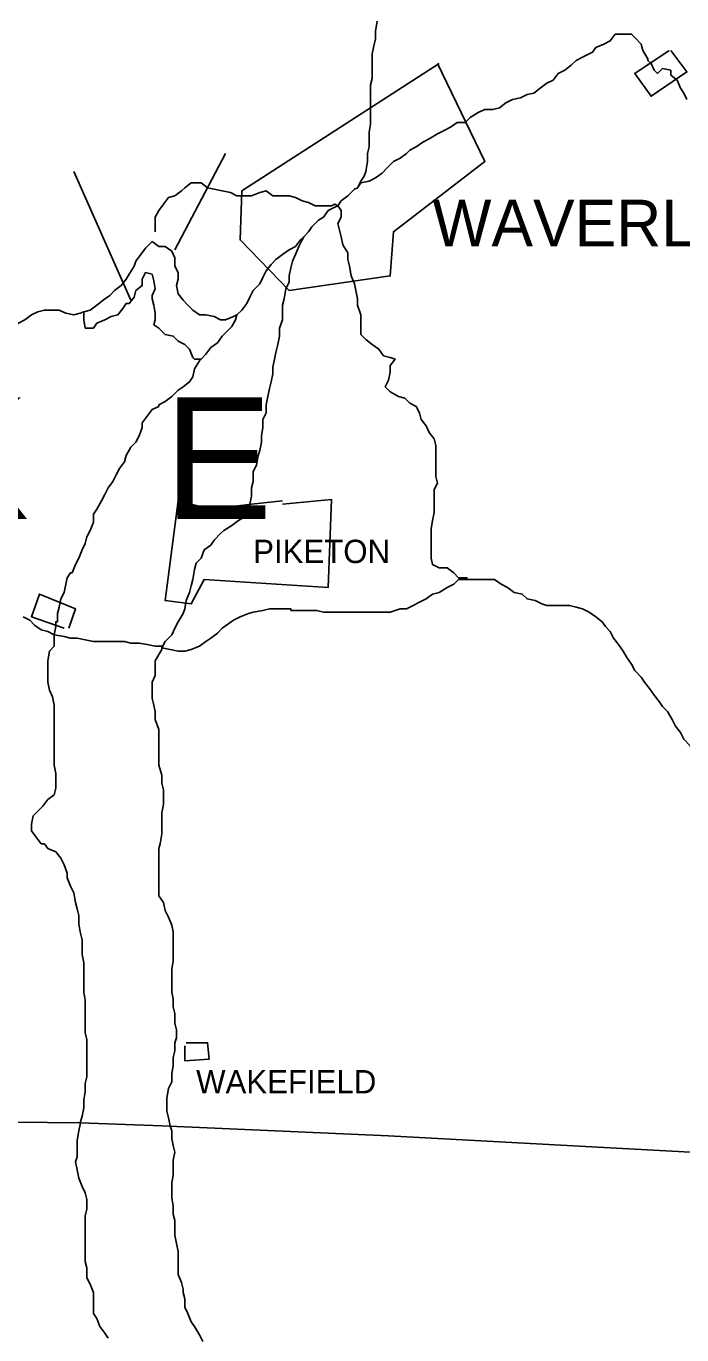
# Model space of a CAD drawing. Extents: x 0 to 34, y 0 to 22.
# Drawn here: x 5.838 to 6.387, y 17.195 to 18.289 of the extents above; entities that cross this region are included whole.
import ezdxf

# ---------------------------------------------------------------- set-up
doc = ezdxf.new("R2010")
doc.units = 0
doc.layers.add('Default', color=7, linetype='Continuous')
doc.layers.add('TR_Turning_Path1', color=7, linetype='Continuous')

msp = doc.modelspace()

# ---------------------------------------------------------------- linework, layer by layer
at = {"layer": 'Default'}
for p, q in [((6.005, 18.1825), (5.9627, 18.102)), ((5.8782, 18.1675), (5.9259, 18.0598))]:
    msp.add_line(p, q, dxfattribs=at)
for points in [[(6.1154, 18.1538), (6.1181, 18.1593), (6.1209, 18.1634), (6.1222, 18.1675), (6.1236, 18.1757), (6.1236, 18.1825), (6.125, 18.1879), (6.125, 18.1947), (6.125, 18.2002), (6.1263, 18.207), (6.1263, 18.2138), (6.1263, 18.2193), (6.1263, 18.2275), (6.1263, 18.2329), (6.1263, 18.2397), (6.1277, 18.2452), (6.1277, 18.252), (6.1277, 18.2575), (6.1277, 18.2656), (6.129, 18.2725), (6.1304, 18.2779), (6.1304, 18.2847), (6.1318, 18.2929)], [(6.1154, 18.1538), (6.1181, 18.1593), (6.1209, 18.1634), (6.1222, 18.1675), (6.1236, 18.1757), (6.1236, 18.1825), (6.125, 18.1879), (6.125, 18.1947), (6.125, 18.2002), (6.1263, 18.207), (6.1263, 18.2138), (6.1263, 18.2193), (6.1263, 18.2275), (6.1263, 18.2329), (6.1263, 18.2397), (6.1277, 18.2452), (6.1277, 18.252), (6.1277, 18.2575), (6.1277, 18.2656), (6.129, 18.2725), (6.1304, 18.2779), (6.1304, 18.2847), (6.1318, 18.2929)], [(6.3581, 18.2615), (6.354, 18.2684), (6.3526, 18.2738), (6.3472, 18.2793), (6.3445, 18.282), (6.3376, 18.282), (6.3308, 18.282), (6.3267, 18.2765), (6.3213, 18.2738), (6.3145, 18.2711), (6.3117, 18.267), (6.3036, 18.2629), (6.2981, 18.2602), (6.294, 18.2561), (6.2886, 18.252), (6.2831, 18.2493), (6.279, 18.2438), (6.2736, 18.2411), (6.2681, 18.237), (6.2627, 18.2329), (6.2572, 18.2316), (6.2517, 18.2288), (6.2449, 18.2275), (6.2395, 18.2247), (6.234, 18.2206), (6.2286, 18.2193), (6.2218, 18.2193), (6.2163, 18.2166), (6.2095, 18.2125), (6.2054, 18.2084), (6.1986, 18.2084), (6.1931, 18.2043), (6.1877, 18.2016), (6.1822, 18.1988), (6.1754, 18.1947), (6.1699, 18.192), (6.1645, 18.1879), (6.159, 18.1852), (6.1563, 18.1825), (6.1509, 18.1784), (6.1454, 18.1757), (6.1399, 18.1702), (6.1359, 18.1661), (6.1304, 18.162), (6.125, 18.1593), (6.1181, 18.1579), (6.1154, 18.1538), (6.1154, 18.1538), (6.1154, 18.1538)], [(6.3758, 18.2684), (6.3472, 18.2493), (6.3608, 18.2302), (6.3908, 18.2506), (6.3772, 18.2684)], [(6.3908, 18.2275), (6.3881, 18.2329), (6.3854, 18.237), (6.3826, 18.2438), (6.3772, 18.2479), (6.3772, 18.252), (6.3704, 18.2534), (6.3663, 18.2493), (6.3635, 18.252), (6.3608, 18.2575), (6.3581, 18.2602), (6.3581, 18.2615)], [(6.1836, 18.2575), (6.0186, 18.1511), (6.0172, 18.1102), (6.0581, 18.0679), (6.1427, 18.0802), (6.1454, 18.117), (6.2218, 18.1757), (6.1822, 18.2575)], [(5.9463, 18.117), (5.9463, 18.1225), (5.9463, 18.1293), (5.9491, 18.1347), (5.9532, 18.1402), (5.9573, 18.1457), (5.9627, 18.147), (5.9682, 18.1511), (5.9709, 18.1538), (5.9763, 18.1579), (5.9804, 18.1579), (5.9845, 18.1579), (5.9845, 18.1579)], [(5.9845, 18.1579), (5.99, 18.1538), (5.9954, 18.1525), (6.0022, 18.1511), (6.0091, 18.1497), (6.0145, 18.147), (6.02, 18.147), (6.0268, 18.147), (6.0336, 18.1497), (6.0391, 18.1511), (6.0445, 18.147), (6.05, 18.147), (6.0581, 18.147), (6.0636, 18.1457), (6.0691, 18.1429), (6.0745, 18.1416), (6.08, 18.1388), (6.0854, 18.1388), (6.0936, 18.1388), (6.0963, 18.1402), (6.099, 18.1388)], [(6.099, 18.1388), (6.1018, 18.1429), (6.1072, 18.147), (6.1127, 18.1525), (6.1154, 18.1538), (6.1154, 18.1538)], [(6.099, 18.1388), (6.1018, 18.1429), (6.1072, 18.147), (6.1127, 18.1525), (6.1154, 18.1538), (6.1154, 18.1538)], [(6.0704, 18.1129), (6.0745, 18.117), (6.0772, 18.1211), (6.0827, 18.1266), (6.0868, 18.1293), (6.0909, 18.1347), (6.0963, 18.1375), (6.099, 18.1388)], [(6.0704, 18.1129), (6.0745, 18.117), (6.0772, 18.1211), (6.0827, 18.1266), (6.0868, 18.1293), (6.0909, 18.1347), (6.0963, 18.1375), (6.099, 18.1388)], [(6.099, 18.1388), (6.1018, 18.1347), (6.1018, 18.1293), (6.099, 18.1238), (6.1004, 18.1184), (6.1018, 18.1129), (6.1031, 18.1061), (6.1072, 18.0993), (6.1072, 18.0938), (6.1086, 18.0884), (6.11, 18.0802), (6.11, 18.0802)], [(5.8864, 18.0502), (5.8918, 18.0516), (5.8973, 18.0557), (5.9027, 18.0598), (5.9082, 18.0639), (5.9123, 18.0679), (5.9177, 18.072), (5.9218, 18.0775), (5.9245, 18.0816), (5.9286, 18.0884), (5.93, 18.0925), (5.9341, 18.0979), (5.9382, 18.1034), (5.9436, 18.1088), (5.9436, 18.1088)], [(5.9436, 18.1088), (5.9491, 18.1048), (5.9545, 18.1048), (5.96, 18.1007), (5.9627, 18.0952), (5.9627, 18.0884), (5.9654, 18.0829), (5.9654, 18.0775), (5.9641, 18.072), (5.9654, 18.0652), (5.9695, 18.0598), (5.9736, 18.0557), (5.9777, 18.0516), (5.9832, 18.0475), (5.9886, 18.0475), (5.9954, 18.0461), (6.0009, 18.0434), (6.005, 18.0434), (6.0118, 18.0461), (6.0145, 18.0475), (6.0145, 18.0475)], [(6.0145, 18.0475), (6.0186, 18.0516), (6.0227, 18.057), (6.0254, 18.0625), (6.0281, 18.0679), (6.0336, 18.0734), (6.0363, 18.0788), (6.0391, 18.0843), (6.0431, 18.0898), (6.0472, 18.0938), (6.0527, 18.0979), (6.0581, 18.102), (6.0636, 18.1048), (6.0677, 18.1102), (6.0704, 18.1129)], [(6.035, 17.9466), (6.0363, 17.9534), (6.0363, 17.9602), (6.0391, 17.9657), (6.0391, 17.9725), (6.0404, 17.9793), (6.0418, 17.9861), (6.0431, 17.9916), (6.0445, 17.9984), (6.0445, 18.0039), (6.0459, 18.0107), (6.0472, 18.0161), (6.0486, 18.0229), (6.05, 18.0298), (6.05, 18.0366), (6.0527, 18.0434), (6.0527, 18.0489), (6.0527, 18.0557), (6.0541, 18.0611), (6.0554, 18.0693), (6.0581, 18.0748), (6.0581, 18.0802), (6.0595, 18.087), (6.0609, 18.0925), (6.0636, 18.0979), (6.0663, 18.1048), (6.0691, 18.1102), (6.0704, 18.1129)], [(5.9245, 18.057), (5.9286, 18.0625), (5.93, 18.0679), (5.9354, 18.072), (5.9354, 18.0775), (5.9382, 18.0829), (5.9436, 18.0816), (5.945, 18.0761), (5.9463, 18.0693), (5.9436, 18.0639), (5.9436, 18.0625), (5.9436, 18.0611)], [(6.11, 18.0802), (6.1127, 18.0734), (6.114, 18.0679), (6.1154, 18.0611), (6.1154, 18.0557), (6.1181, 18.0475), (6.1181, 18.0434), (6.1181, 18.0366), (6.1181, 18.0311), (6.1222, 18.027), (6.1277, 18.0229), (6.1331, 18.0189), (6.1372, 18.0134), (6.1427, 18.012), (6.1468, 18.0107), (6.1427, 18.0052), (6.1427, 17.9998), (6.1413, 17.993), (6.1386, 17.9875), (6.1386, 17.9875), (6.1386, 17.9875)], [(5.8864, 18.0502), (5.8864, 18.0434), (5.8877, 18.0366), (5.8945, 18.0366), (5.8973, 18.0407), (5.9041, 18.0434), (5.9095, 18.0461), (5.915, 18.0475), (5.9191, 18.0529), (5.9218, 18.057), (5.9245, 18.057)], [(5.9436, 18.0611), (5.945, 18.0557), (5.9463, 18.0489), (5.9463, 18.0434), (5.945, 18.0393), (5.9491, 18.0366), (5.9532, 18.0325), (5.9545, 18.0311), (5.9545, 18.0311)], [(5.8264, 18.0366), (5.8318, 18.0407), (5.8373, 18.0434), (5.8427, 18.0475), (5.8482, 18.0502), (5.8536, 18.0516), (5.8604, 18.0516), (5.8659, 18.0516), (5.8714, 18.0489), (5.8782, 18.0475), (5.8836, 18.0489), (5.8864, 18.0502)], [(5.9845, 18.0107), (5.9886, 18.0148), (5.9927, 18.0202), (5.9982, 18.0243), (6.0022, 18.0298), (6.0063, 18.0339), (6.0104, 18.0379), (6.0132, 18.0434), (6.0145, 18.0475)], [(5.9545, 18.0311), (5.9613, 18.0298), (5.9654, 18.0257), (5.9709, 18.0229), (5.975, 18.0189), (5.9777, 18.012), (5.9791, 18.0107), (5.9845, 18.0107), (5.9845, 18.0107)], [(5.9491, 17.9725), (5.9545, 17.9752), (5.96, 17.9793), (5.9654, 17.9848), (5.9695, 17.9875), (5.975, 17.9916), (5.9777, 17.9957), (5.9791, 18.0025), (5.9832, 18.0093), (5.9845, 18.0107)], [(6.1386, 17.9875), (6.1427, 17.9834), (6.1495, 17.9793), (6.1549, 17.978), (6.159, 17.9739), (6.1645, 17.9711), (6.1672, 17.9657), (6.1686, 17.9602), (6.1727, 17.9548), (6.1754, 17.9493), (6.1795, 17.9439), (6.1809, 17.9384), (6.1809, 17.9316), (6.1809, 17.9248), (6.1809, 17.9193), (6.1809, 17.9125), (6.1822, 17.9071)], [(5.8768, 17.8321), (5.8795, 17.8389), (5.8823, 17.8443), (5.885, 17.8512), (5.8877, 17.8566), (5.8891, 17.8621), (5.8918, 17.8675), (5.8945, 17.8743), (5.8945, 17.8812), (5.8973, 17.8852), (5.9013, 17.8921), (5.9041, 17.8975), (5.9068, 17.903), (5.9109, 17.9084), (5.9136, 17.9139), (5.9163, 17.9193), (5.9204, 17.9248), (5.9218, 17.9302), (5.9259, 17.9371), (5.93, 17.9411), (5.9327, 17.9466), (5.9354, 17.9534), (5.9354, 17.9575), (5.9395, 17.963), (5.9436, 17.9684), (5.9491, 17.9711), (5.9491, 17.9725)], [(5.9518, 17.7694), (5.9545, 17.7748), (5.96, 17.7803), (5.9627, 17.7857), (5.9654, 17.7912), (5.9695, 17.798), (5.9709, 17.8021), (5.9722, 17.8089), (5.975, 17.8157), (5.9763, 17.8212), (5.9777, 17.8266), (5.9791, 17.8348), (5.9804, 17.8402), (5.9845, 17.8443), (5.9872, 17.8512), (5.9927, 17.8552), (5.9954, 17.8593), (6.0009, 17.8648), (6.0036, 17.8675), (6.0104, 17.8716), (6.0159, 17.8757), (6.02, 17.8784), (6.0241, 17.8839), (6.0254, 17.8893), (6.0268, 17.8961), (6.0268, 17.903), (6.0281, 17.9084), (6.0281, 17.9166), (6.0309, 17.9221), (6.0322, 17.9302), (6.0336, 17.9343), (6.035, 17.9411), (6.035, 17.9452), (6.035, 17.9466)], [(6.1822, 17.9071), (6.1795, 17.9016), (6.1795, 17.8961), (6.1795, 17.8893), (6.1795, 17.8825), (6.1781, 17.8757), (6.1768, 17.8689), (6.1768, 17.8634), (6.1768, 17.8566), (6.1768, 17.8512), (6.1768, 17.8443), (6.1781, 17.8389), (6.1836, 17.8362), (6.1904, 17.8362), (6.1958, 17.8321), (6.1999, 17.828), (6.2068, 17.828), (6.2068, 17.8266)], [(6.0527, 17.8893), (6.0936, 17.8934), (6.0909, 17.8198), (5.9872, 17.8266), (5.9763, 17.8062), (5.9545, 17.8089), (5.9654, 17.8921), (5.9927, 17.8852), (6.0268, 17.8893), (6.0527, 17.8921)], [(5.8645, 17.7912), (5.8645, 17.798), (5.8659, 17.8034), (5.8673, 17.8103), (5.87, 17.8157), (5.8714, 17.8225), (5.8727, 17.828), (5.8754, 17.8321), (5.8768, 17.8321)], [(6.0595, 17.8007), (6.0663, 17.8007), (6.0745, 17.8007), (6.0813, 17.8007), (6.0868, 17.7993), (6.0936, 17.7993), (6.1004, 17.7993), (6.1072, 17.7993), (6.1127, 17.7993), (6.1181, 17.7993), (6.1263, 17.7993), (6.1318, 17.7993), (6.1386, 17.7993), (6.1427, 17.7993), (6.1509, 17.8021), (6.1563, 17.8021), (6.1618, 17.8048), (6.1672, 17.8075), (6.1727, 17.8103), (6.1781, 17.8143), (6.1836, 17.8157), (6.1904, 17.8198), (6.1958, 17.8225), (6.1999, 17.8266), (6.2054, 17.8266), (6.2068, 17.8266)], [(6.0595, 17.8007), (6.0663, 17.8007), (6.0745, 17.8007), (6.0813, 17.8007), (6.0868, 17.7993), (6.0936, 17.7993), (6.1004, 17.7993), (6.1072, 17.7993), (6.1127, 17.7993), (6.1181, 17.7993), (6.1263, 17.7993), (6.1318, 17.7993), (6.1386, 17.7993), (6.1427, 17.7993), (6.1509, 17.8021), (6.1563, 17.8021), (6.1618, 17.8048), (6.1672, 17.8075), (6.1727, 17.8103), (6.1781, 17.8143), (6.1836, 17.8157), (6.1904, 17.8198), (6.1958, 17.8225), (6.1999, 17.8266), (6.2054, 17.8266), (6.2068, 17.8266)], [(6.2068, 17.8266), (6.2136, 17.8266), (6.219, 17.8266), (6.2245, 17.8266), (6.2299, 17.8266), (6.2354, 17.8225), (6.2408, 17.8198), (6.2463, 17.8157), (6.2531, 17.8143), (6.2572, 17.8103), (6.264, 17.8089), (6.2695, 17.8062), (6.2736, 17.8048), (6.2804, 17.8048), (6.2872, 17.8048), (6.2927, 17.8048), (6.2981, 17.8034), (6.3036, 17.8021), (6.309, 17.7993), (6.309, 17.7993)], [(6.2068, 17.8266), (6.2136, 17.8266), (6.219, 17.8266), (6.2245, 17.8266), (6.2299, 17.8266), (6.2354, 17.8225), (6.2408, 17.8198), (6.2463, 17.8157), (6.2531, 17.8143), (6.2572, 17.8103), (6.264, 17.8089), (6.2695, 17.8062), (6.2736, 17.8048), (6.2804, 17.8048), (6.2872, 17.8048), (6.2927, 17.8048), (6.2981, 17.8034), (6.3036, 17.8021), (6.309, 17.7993), (6.309, 17.7993)], [(5.87, 17.7857), (5.8427, 17.7953), (5.8495, 17.8143), (5.8795, 17.8021), (5.8741, 17.7857)], [(5.9518, 17.7694), (5.9586, 17.768), (5.9654, 17.7666), (5.9709, 17.7666), (5.9763, 17.768), (5.9832, 17.7707), (5.9886, 17.7748), (5.9927, 17.7775), (5.9982, 17.7816), (6.0022, 17.7857), (6.0077, 17.7898), (6.0118, 17.7925), (6.0172, 17.7953), (6.0241, 17.798), (6.0281, 17.7993), (6.0363, 17.8007), (6.0418, 17.8021), (6.0486, 17.8021), (6.0541, 17.8021), (6.0595, 17.8021), (6.0595, 17.8007)], [(5.9518, 17.7694), (5.9586, 17.768), (5.9654, 17.7666), (5.9709, 17.7666), (5.9763, 17.768), (5.9832, 17.7707), (5.9886, 17.7748), (5.9927, 17.7775), (5.9982, 17.7816), (6.0022, 17.7857), (6.0077, 17.7898), (6.0118, 17.7925), (6.0172, 17.7953), (6.0241, 17.798), (6.0281, 17.7993), (6.0363, 17.8007), (6.0418, 17.8021), (6.0486, 17.8021), (6.0541, 17.8021), (6.0595, 17.8021), (6.0595, 17.8007)], [(5.8359, 17.7953), (5.8414, 17.7925), (5.8454, 17.7884), (5.8509, 17.7843), (5.8564, 17.783), (5.8618, 17.7803), (5.8618, 17.7803), (5.8618, 17.7803)], [(5.8359, 17.7953), (5.8414, 17.7925), (5.8454, 17.7884), (5.8509, 17.7843), (5.8564, 17.783), (5.8618, 17.7803), (5.8618, 17.7803), (5.8618, 17.7803)], [(5.8618, 17.7803), (5.8632, 17.7871), (5.8632, 17.7912), (5.8645, 17.7912)], [(6.309, 17.7993), (6.3145, 17.7953), (6.3199, 17.7912), (6.3226, 17.7871), (6.3267, 17.783), (6.3295, 17.7775), (6.3336, 17.7721), (6.3376, 17.7666), (6.3404, 17.7612), (6.3445, 17.7557), (6.3472, 17.7503), (6.3526, 17.7448), (6.3554, 17.7407), (6.3595, 17.7353), (6.3635, 17.7298), (6.3676, 17.7244), (6.3704, 17.7203), (6.3745, 17.7162), (6.3745, 17.7162)], [(6.309, 17.7993), (6.3145, 17.7953), (6.3199, 17.7912), (6.3226, 17.7871), (6.3267, 17.783), (6.3295, 17.7775), (6.3336, 17.7721), (6.3376, 17.7666), (6.3404, 17.7612), (6.3445, 17.7557), (6.3472, 17.7503), (6.3526, 17.7448), (6.3554, 17.7407), (6.3595, 17.7353), (6.3635, 17.7298), (6.3676, 17.7244), (6.3704, 17.7203), (6.3745, 17.7162), (6.3745, 17.7162)], [(5.8509, 17.6057), (5.8468, 17.6112), (5.8427, 17.6166), (5.8427, 17.6221), (5.8441, 17.6289), (5.8482, 17.633), (5.8523, 17.6371), (5.8564, 17.6426), (5.8618, 17.6466), (5.8632, 17.6521), (5.8632, 17.6576), (5.8632, 17.6644), (5.8618, 17.6712), (5.8618, 17.678), (5.8618, 17.6848), (5.8618, 17.6903), (5.8618, 17.6971), (5.8618, 17.7025), (5.8618, 17.7094), (5.8618, 17.7162), (5.8618, 17.7216), (5.8604, 17.7284), (5.8577, 17.7339), (5.8564, 17.7407), (5.8564, 17.7462), (5.8564, 17.753), (5.8564, 17.7584), (5.8577, 17.7666), (5.8618, 17.7707), (5.8618, 17.7775), (5.8618, 17.7789), (5.8618, 17.7803)], [(5.8618, 17.7803), (5.87, 17.7789), (5.8754, 17.7775), (5.8809, 17.7775), (5.8877, 17.7762), (5.8945, 17.7748), (5.9, 17.7748), (5.9068, 17.7748), (5.9136, 17.7748), (5.9204, 17.7748), (5.9259, 17.7734), (5.9327, 17.7734), (5.9395, 17.7721), (5.9463, 17.7707), (5.9518, 17.7707), (5.9518, 17.7694)], [(5.8618, 17.7803), (5.87, 17.7789), (5.8754, 17.7775), (5.8809, 17.7775), (5.8877, 17.7762), (5.8945, 17.7748), (5.9, 17.7748), (5.9068, 17.7748), (5.9136, 17.7748), (5.9204, 17.7748), (5.9259, 17.7734), (5.9327, 17.7734), (5.9395, 17.7721), (5.9463, 17.7707), (5.9518, 17.7707), (5.9518, 17.7694)], [(5.9518, 17.6262), (5.9518, 17.6316), (5.9532, 17.6385), (5.9532, 17.6453), (5.9532, 17.6507), (5.9518, 17.6562), (5.9518, 17.663), (5.9491, 17.6712), (5.9491, 17.6766), (5.9491, 17.6835), (5.9491, 17.6889), (5.9491, 17.6957), (5.9491, 17.7012), (5.9463, 17.7094), (5.9463, 17.7162), (5.945, 17.7216), (5.9436, 17.7271), (5.9436, 17.7339), (5.9436, 17.7407), (5.9463, 17.7462), (5.9463, 17.753), (5.9463, 17.7584), (5.9491, 17.7639), (5.9518, 17.768), (5.9518, 17.7694)], [(6.3745, 17.7162), (6.3785, 17.7094), (6.3813, 17.7039), (6.3854, 17.6985), (6.3881, 17.693), (6.3935, 17.6875), (6.3963, 17.6835), (6.4004, 17.6794), (6.4045, 17.6725), (6.4085, 17.6685), (6.4126, 17.663), (6.4194, 17.6603), (6.4249, 17.6576), (6.4304, 17.6562), (6.4372, 17.6548), (6.4426, 17.6548), (6.4494, 17.6535), (6.4563, 17.6521), (6.4617, 17.6521), (6.4685, 17.6521), (6.4699, 17.6521)], [(6.3745, 17.7162), (6.3785, 17.7094), (6.3813, 17.7039), (6.3854, 17.6985), (6.3881, 17.693), (6.3935, 17.6875), (6.3963, 17.6835), (6.4004, 17.6794), (6.4045, 17.6725), (6.4085, 17.6685), (6.4126, 17.663), (6.4194, 17.6603), (6.4249, 17.6576), (6.4304, 17.6562), (6.4372, 17.6548), (6.4426, 17.6548), (6.4494, 17.6535), (6.4563, 17.6521), (6.4617, 17.6521), (6.4685, 17.6521), (6.4699, 17.6521)], [(5.9586, 17.3699), (5.9573, 17.3767), (5.9559, 17.3821), (5.9559, 17.389), (5.9559, 17.393), (5.9573, 17.4012), (5.96, 17.4067), (5.96, 17.4135), (5.9613, 17.4203), (5.9613, 17.4271), (5.9627, 17.4326), (5.9627, 17.4394), (5.9641, 17.4435), (5.9641, 17.4503), (5.9627, 17.4558), (5.9627, 17.4639), (5.9613, 17.4694), (5.9613, 17.4762), (5.96, 17.4817), (5.96, 17.4885), (5.96, 17.4953), (5.96, 17.5008), (5.9613, 17.5076), (5.9613, 17.513), (5.9613, 17.5198), (5.9613, 17.5253), (5.9613, 17.5321), (5.96, 17.5376), (5.9573, 17.5444), (5.9545, 17.5498), (5.9532, 17.5567), (5.9491, 17.5621), (5.9491, 17.5689), (5.9491, 17.5744), (5.9491, 17.5812), (5.9491, 17.588), (5.9491, 17.5948), (5.9491, 17.6017), (5.9504, 17.6057), (5.9518, 17.6139), (5.9518, 17.6194), (5.9518, 17.6248), (5.9518, 17.6248), (5.9518, 17.6262)], [(5.8836, 17.3726), (5.885, 17.378), (5.8864, 17.3849), (5.8864, 17.3917), (5.8877, 17.3985), (5.8877, 17.4053), (5.8891, 17.4108), (5.8891, 17.4162), (5.8891, 17.4244), (5.8891, 17.4299), (5.8891, 17.4353), (5.8891, 17.4421), (5.8877, 17.4476), (5.8877, 17.4558), (5.8877, 17.4612), (5.8877, 17.468), (5.8877, 17.4749), (5.8864, 17.4817), (5.8864, 17.4871), (5.8864, 17.4926), (5.8864, 17.4994), (5.8864, 17.5062), (5.885, 17.513), (5.885, 17.5198), (5.885, 17.5253), (5.8836, 17.5321), (5.8823, 17.5389), (5.8823, 17.5458), (5.8809, 17.5512), (5.8795, 17.5567), (5.8782, 17.5648), (5.8754, 17.5703), (5.8727, 17.5771), (5.8727, 17.5812), (5.87, 17.588), (5.8673, 17.5935), (5.8632, 17.5989), (5.8564, 17.6017), (5.8536, 17.6057), (5.8523, 17.6057), (5.8509, 17.6057)], [(5.9709, 17.4367), (5.9709, 17.4244), (5.9913, 17.4258), (5.99, 17.4394), (5.9722, 17.4394)], [(5.296, 17.389), (5.4378, 17.3821), (5.5605, 17.378), (5.7473, 17.374), (5.8836, 17.3726), (5.9518, 17.3699), (6.1413, 17.3617), (6.4194, 17.3467), (6.5299, 17.3399), (6.6894, 17.329), (6.7235, 17.3262)], [(5.8945, 17.2185), (5.8945, 17.2253), (5.8945, 17.2308), (5.8918, 17.2376), (5.8891, 17.2431), (5.8891, 17.2513), (5.8877, 17.2567), (5.8877, 17.2635), (5.8877, 17.2703), (5.8877, 17.2758), (5.8877, 17.2826), (5.8877, 17.2881), (5.8877, 17.2949), (5.8891, 17.3003), (5.8891, 17.3085), (5.8877, 17.314), (5.885, 17.3194), (5.8823, 17.3262), (5.8809, 17.3331), (5.8795, 17.3399), (5.8809, 17.344), (5.8809, 17.3508), (5.8809, 17.3576), (5.8823, 17.3658), (5.8836, 17.3712), (5.8836, 17.3726)], [(5.9695, 17.2335), (5.9682, 17.239), (5.9654, 17.2458), (5.9654, 17.2513), (5.9654, 17.2594), (5.9654, 17.2649), (5.9641, 17.2717), (5.9627, 17.2785), (5.9627, 17.284), (5.9627, 17.2908), (5.9613, 17.2962), (5.9613, 17.3031), (5.96, 17.3099), (5.96, 17.3167), (5.96, 17.3221), (5.9613, 17.329), (5.9613, 17.3344), (5.9613, 17.3412), (5.9627, 17.3481), (5.9613, 17.3535), (5.96, 17.359), (5.96, 17.3658), (5.9586, 17.3699), (5.9586, 17.3699)], [(5.9859, 17.1899), (5.9832, 17.1954), (5.9791, 17.2022), (5.9763, 17.2063), (5.9736, 17.2131), (5.9709, 17.2185), (5.9709, 17.2253), (5.9695, 17.2308), (5.9695, 17.2322), (5.9695, 17.2335)], [(5.9068, 17.1926), (5.9041, 17.1967), (5.9, 17.2022), (5.8973, 17.209), (5.8945, 17.2131), (5.8945, 17.2185), (5.8945, 17.2185)]]:
    msp.add_lwpolyline(points, dxfattribs=at)

# ---------------------------------------------------------------- texts
for s, height, p in [('WAVERLY', 0.039, (6.1781, 18.1048)), ('PIKETON', 0.0195, (6.0281, 17.8402)), ('WAKEFIELD', 0.0195, (5.9804, 17.3971))]:
    msp.add_text(s, height=height, dxfattribs=at).set_placement(p)
at = {"layer": 'TR_Turning_Path1'}
msp.add_text('P   I   K   E', height=0.101489, dxfattribs=at).set_placement((5.3955, 17.8771))

doc.saveas('drawing.dxf')
